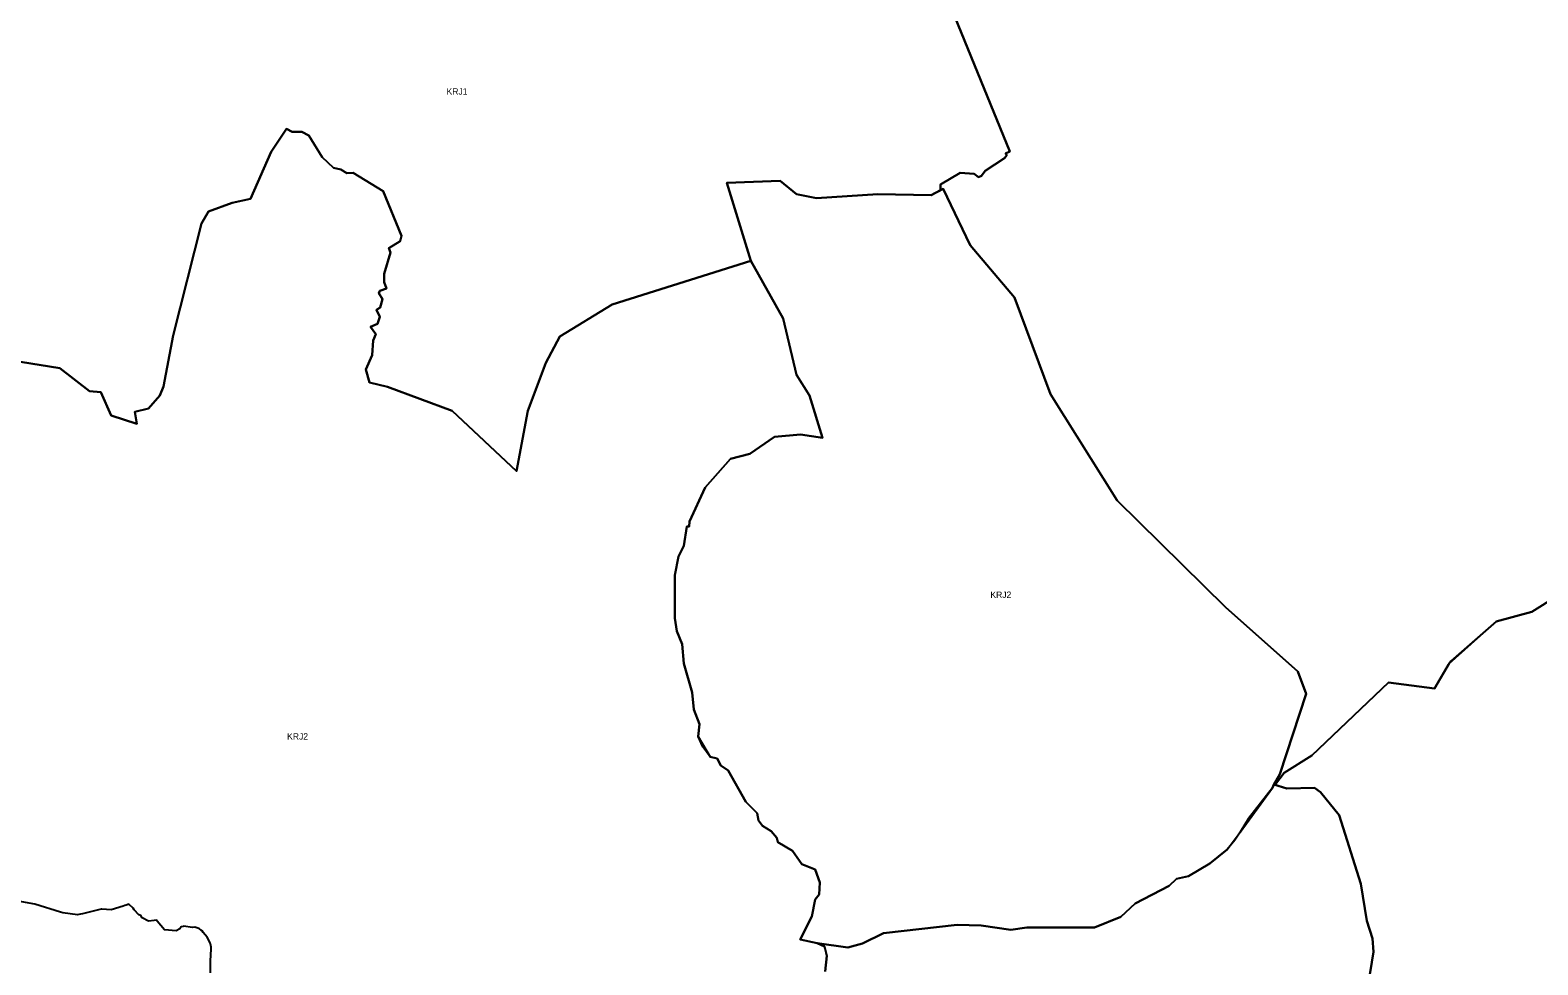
# Model space of a CAD drawing. Extents: x -563112 to -465432, y -1206259 to -1132144.
# Drawn here: x -530418 to -518635, y -1199871 to -1192564 of the extents above; entities that cross this region are included whole.
import ezdxf

# ---------------------------------------------------------------- set-up
doc = ezdxf.new("R2010")
doc.units = 0
doc.layers.add('krajiny', color=7, linetype='Continuous')

msp = doc.modelspace()

# ---------------------------------------------------------------- linework, layer by layer
at = {"layer": 'krajiny'}
for points in [[(-523418.06, -1191902.54), (-522761.43, -1193511.74), (-522794.17, -1193528.61), (-522785.36, -1193540.72), (-522802.15, -1193565.25), (-522953.29, -1193664.26), (-522982.73, -1193703.31), (-523005.08, -1193713.83), (-523038.89, -1193687.35), (-523150.39, -1193680.19), (-523302.16, -1193771.65), (-523304.36, -1193815.21), (-523376.64, -1193852.94), (-523793.12, -1193845.08), (-524272.46, -1193876.52), (-524429.63, -1193845.08), (-524555.36, -1193742.89), (-524971.83, -1193758.61), (-524786.81, -1194367.85), (-525868.44, -1194707.54), (-526277.06, -1194959.08), (-526387.08, -1195163.46), (-526528.52, -1195540.77), (-526618.11, -1196012.41), (-527121.03, -1195540.77), (-527623.94, -1195352.12), (-527764.96, -1195317.9), (-527793.76, -1195216.57), (-527744.87, -1195104.26), (-527736.36, -1194991.17), (-527715.62, -1194940.49), (-527757.63, -1194883.24), (-527703.74, -1194858.95), (-527684.15, -1194804.72), (-527711.6, -1194750.63), (-527683.3, -1194731.18), (-527663.88, -1194667.64), (-527692.83, -1194620.1), (-527684.95, -1194600.81), (-527632.23, -1194583.13), (-527651.48, -1194532.72), (-527651.31, -1194469.08), (-527601.47, -1194303.08), (-527614.02, -1194267.82), (-527527.04, -1194212.48), (-527516.36, -1194171.48), (-527657.83, -1193822.29), (-527892.53, -1193680.13), (-527943.07, -1193681.91), (-527989.51, -1193652.24), (-528047.42, -1193639.62), (-528136.43, -1193556.5), (-528241.08, -1193387.67), (-528295.36, -1193359.48), (-528371.43, -1193359.48), (-528413.89, -1193336.46), (-528534.49, -1193513.77), (-528695.13, -1193882.58), (-528838.68, -1193912.96), (-529022.96, -1193981.78), (-529078.83, -1194074.99), (-529300.43, -1194951.12), (-529375.09, -1195348.92), (-529405.38, -1195420.07), (-529494.14, -1195520.59), (-529600.6, -1195547.32), (-529583.79, -1195642.1), (-529785.69, -1195577.05), (-529866.28, -1195393.12), (-529955.14, -1195385.59), (-530186.4, -1195205.83), (-530493.36, -1195157.45)], [(-518486.29, -1196988.95), (-518682.09, -1197112.28), (-518959.55, -1197187.8), (-519315.92, -1197497.27), (-519326.63, -1197515.52), (-519441.35, -1197710.99), (-519803.09, -1197663.65), (-520401.45, -1198233.26), (-520617.16, -1198369.87), (-520684.89, -1198459.31), (-520698.97, -1198460.73), (-520650.68, -1198380.09), (-520446.37, -1197751.23), (-520509.24, -1197578.3), (-521075.02, -1197075.22), (-521923.69, -1196241.99), (-522442.32, -1195408.75), (-522725.21, -1194654.13), (-523070.97, -1194245.38), (-523282.17, -1193803.63), (-523304.36, -1193815.21), (-523302.16, -1193771.65), (-523150.39, -1193680.19), (-523038.89, -1193687.35), (-523005.08, -1193713.83), (-522982.73, -1193703.31), (-522953.29, -1193664.26), (-522802.15, -1193565.25), (-522785.36, -1193540.72), (-522794.17, -1193528.61), (-522761.43, -1193511.74), (-523418.06, -1191902.54)], [(-530493.36, -1195157.45), (-530186.4, -1195205.83), (-529955.14, -1195385.59), (-529866.28, -1195393.12), (-529785.69, -1195577.05), (-529583.79, -1195642.1), (-529600.6, -1195547.32), (-529494.14, -1195520.59), (-529405.38, -1195420.07), (-529375.09, -1195348.92), (-529300.43, -1194951.12), (-529078.83, -1194074.99), (-529022.96, -1193981.78), (-528838.68, -1193912.96), (-528695.13, -1193882.58), (-528534.49, -1193513.77), (-528413.89, -1193336.46), (-528371.43, -1193359.48), (-528295.36, -1193359.48), (-528241.08, -1193387.67), (-528136.43, -1193556.5), (-528047.42, -1193639.62), (-527989.51, -1193652.24), (-527943.07, -1193681.91), (-527892.53, -1193680.13), (-527657.83, -1193822.29), (-527516.36, -1194171.48), (-527527.04, -1194212.48), (-527614.02, -1194267.82), (-527601.47, -1194303.08), (-527651.31, -1194469.08), (-527651.48, -1194532.72), (-527632.23, -1194583.13), (-527684.95, -1194600.81), (-527692.83, -1194620.1), (-527663.88, -1194667.64), (-527683.3, -1194731.18), (-527711.6, -1194750.63), (-527684.15, -1194804.72), (-527703.74, -1194858.95), (-527757.63, -1194883.24), (-527715.62, -1194940.49), (-527736.36, -1194991.17), (-527744.87, -1195104.26), (-527793.76, -1195216.57), (-527764.96, -1195317.9), (-527623.94, -1195352.12), (-527121.03, -1195540.77), (-526618.11, -1196012.41), (-526528.52, -1195540.77), (-526387.08, -1195163.46), (-526277.06, -1194959.08), (-525868.44, -1194707.54), (-524786.81, -1194367.85), (-524532.47, -1194816.74), (-524429.35, -1195258.69), (-524326.23, -1195420.74), (-524224.75, -1195751.16), (-524397.23, -1195725.56), (-524599.31, -1195743), (-524792.91, -1195876), (-524943.9, -1195915.3), (-525142.51, -1196139.3), (-525265.52, -1196405.49), (-525266.95, -1196443.12), (-525285.65, -1196444.36), (-525307.92, -1196595.56), (-525349.77, -1196678.33), (-525380, -1196824.04), (-525378.23, -1197160.97), (-525362.86, -1197262.97), (-525322.2, -1197364.2), (-525310.08, -1197514.34), (-525243.98, -1197741.45), (-525231.48, -1197875.54), (-525186.79, -1197989.51), (-525197.97, -1198086.96), (-525104.2, -1198244.71), (-525048.55, -1198258.84), (-525019.46, -1198312.05), (-524963.94, -1198350.92), (-524825.25, -1198596.33), (-524736.14, -1198684.6), (-524725.06, -1198743.62), (-524693.61, -1198783.37), (-524625.58, -1198825.41), (-524582.79, -1198878.49), (-524575.09, -1198912.48), (-524460.02, -1198980.33), (-524387.13, -1199083.56), (-524282.35, -1199126.61), (-524247.07, -1199227.64), (-524250.78, -1199321.57), (-524282.67, -1199360.04), (-524307.52, -1199493.18), (-524400.53, -1199674.14), (-524267.39, -1199701.71), (-524210.71, -1199727.29), (-524191.55, -1199801.24), (-524205.08, -1199924.03)], [(-519961.63, -1200027.43), (-519919.15, -1199768.91), (-519927.68, -1199665.89), (-519971.87, -1199527.5), (-520017.54, -1199237.84), (-520188.63, -1198701.77), (-520333.82, -1198522.5), (-520379.3, -1198487.37), (-520595.68, -1198493.4), (-520698.97, -1198460.73), (-520684.89, -1198459.31), (-520617.16, -1198369.87), (-520401.45, -1198233.26), (-519803.09, -1197663.65), (-519441.35, -1197710.99), (-519333.88, -1197521.99), (-519326.63, -1197515.52), (-518959.55, -1197187.8), (-518682.09, -1197112.28), (-518486.29, -1196988.95)], [(-524205.08, -1199924.03), (-524191.55, -1199801.24), (-524205.84, -1199744.36), (-524210.71, -1199727.29), (-524267.39, -1199701.71), (-524027.1, -1199734.37), (-523913.96, -1199704.94), (-523748.47, -1199623.14), (-523171.69, -1199558.84), (-522985.5, -1199562.99), (-522752.38, -1199597.91), (-522627.8, -1199580.04), (-522100.4, -1199578.91), (-521892.6, -1199496.75), (-521782.98, -1199392.42), (-521514.83, -1199254.03), (-521459.19, -1199198.74), (-521365.75, -1199177.13), (-521198.82, -1199080.12), (-521062.52, -1198970.73), (-520962.15, -1198833.1), (-520709.3, -1198486.38), (-520698.97, -1198460.73), (-520595.68, -1198493.4), (-520379.3, -1198487.37), (-520333.82, -1198522.5), (-520188.63, -1198701.77), (-520017.54, -1199237.84), (-519971.87, -1199527.5), (-519927.68, -1199665.89), (-519919.15, -1199768.91), (-519961.63, -1200027.43)], [(-529007.49, -1199934.56), (-529008.07, -1199869.56), (-529007.24, -1199842.92), (-529004.2, -1199745.28), (-529004.08, -1199741.3), (-529003.8, -1199732.25), (-529006.86, -1199719.68), (-529007.22, -1199706.27), (-529010.94, -1199700.46), (-529014.01, -1199694.53), (-529034.82, -1199654.33), (-529065.7, -1199617.42), (-529074.17, -1199606.27), (-529076.78, -1199602.84), (-529077.56, -1199601.56), (-529095.94, -1199588.38), (-529097.81, -1199587.78), (-529099.21, -1199585.88), (-529106.68, -1199584.87), (-529130.41, -1199575.55), (-529148.19, -1199579.26), (-529220.06, -1199569.55), (-529223.07, -1199571.5), (-529237.58, -1199573.1), (-529249.19, -1199588.45), (-529275.87, -1199605.75), (-529367.22, -1199597.14), (-529425.18, -1199530.31), (-529425.39, -1199530.01), (-529431.15, -1199523.23), (-529431.31, -1199523.24), (-529431.73, -1199522.76), (-529448.65, -1199524.41), (-529449.06, -1199524.44), (-529449.31, -1199524.48), (-529493.17, -1199528.76), (-529543.2, -1199504.32), (-529554.25, -1199486.45), (-529567.57, -1199479.33), (-529604.56, -1199441.29), (-529612.02, -1199428.36), (-529643.39, -1199398.69), (-529645.5, -1199399.2), (-529646.61, -1199398.06), (-529666.97, -1199404.45), (-529679.07, -1199407.41), (-529690.22, -1199411.75), (-529784.71, -1199441.42), (-529857.14, -1199435.35), (-529860.06, -1199435.06), (-529860.19, -1199435.1), (-529862.06, -1199434.94), (-530009.49, -1199471.5), (-530023.71, -1199474.05), (-530036.93, -1199478), (-530048.63, -1199479.76), (-530162.56, -1199465.61), (-530181.46, -1199460.31), (-530381.69, -1199396.1), (-530510.57, -1199373.36)]]:
    msp.add_lwpolyline(points, dxfattribs=at)
msp.add_lwpolyline([(-524429.63, -1193845.08), (-524272.46, -1193876.52), (-523793.12, -1193845.08), (-523376.64, -1193852.94), (-523282.17, -1193803.63), (-523070.97, -1194245.38), (-522725.21, -1194654.13), (-522442.32, -1195408.75), (-521923.69, -1196241.99), (-521075.02, -1197075.22), (-520509.24, -1197578.3), (-520446.37, -1197751.23), (-520650.68, -1198380.09), (-520698.97, -1198460.73), (-520709.3, -1198486.38), (-520895.84, -1198726.26), (-520962.15, -1198833.1), (-521001.91, -1198897.16), (-521062.52, -1198970.73), (-521198.82, -1199080.12), (-521365.75, -1199177.13), (-521459.19, -1199198.74), (-521514.83, -1199254.03), (-521782.98, -1199392.42), (-521892.6, -1199496.75), (-522100.4, -1199578.91), (-522627.8, -1199580.04), (-522752.38, -1199597.91), (-522985.5, -1199562.99), (-523171.69, -1199558.84), (-523748.47, -1199623.14), (-523913.96, -1199704.94), (-524027.1, -1199734.37), (-524267.39, -1199701.71), (-524400.53, -1199674.14), (-524307.52, -1199493.18), (-524282.67, -1199360.04), (-524250.78, -1199321.57), (-524247.07, -1199227.64), (-524282.35, -1199126.61), (-524387.13, -1199083.56), (-524460.02, -1198980.33), (-524575.09, -1198912.48), (-524582.79, -1198878.49), (-524625.58, -1198825.41), (-524693.61, -1198783.37), (-524725.06, -1198743.62), (-524736.14, -1198684.6), (-524825.25, -1198596.33), (-524963.94, -1198350.92), (-525019.46, -1198312.05), (-525048.55, -1198258.84), (-525104.2, -1198244.71), (-525161.4, -1198165.52), (-525197.97, -1198086.96), (-525186.79, -1197989.51), (-525231.48, -1197875.54), (-525243.98, -1197741.45), (-525310.08, -1197514.34), (-525322.2, -1197364.2), (-525362.86, -1197262.97), (-525378.23, -1197160.97), (-525380, -1196824.04), (-525349.77, -1196678.33), (-525307.92, -1196595.56), (-525285.65, -1196444.36), (-525266.95, -1196443.12), (-525265.52, -1196405.49), (-525142.51, -1196139.3), (-524943.9, -1195915.3), (-524792.91, -1195876), (-524599.31, -1195743), (-524397.23, -1195725.56), (-524224.75, -1195751.16), (-524326.23, -1195420.74), (-524429.35, -1195258.69), (-524532.47, -1194816.74), (-524786.81, -1194367.85), (-524971.83, -1193758.61), (-524555.36, -1193742.89)], close=True, dxfattribs=at)

# ---------------------------------------------------------------- texts
for s, p in [('KRJ1', (-527163.37, -1193068.08)), ('KRJ2', (-522913.19, -1197002.87)), ('KRJ2', (-528409.74, -1198110.34))]:
    msp.add_text(s, height=50, dxfattribs=at).set_placement(p)

doc.saveas('drawing.dxf')
